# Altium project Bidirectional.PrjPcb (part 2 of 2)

## Sheet bidirectional-Phase2&3.SchDoc: Phase 2 and 3
size 431 x 279 mm; Date: Not shown in title block; ApprovedBy: Not shown in title block; CheckedBy: Not shown in title block; Author: Not shown in title block; CompanyName: Not shown in title block; Engineer: Not shown in title block; Organization: Not shown in title block; Address1: Not shown in title block; Address2: Not shown in title block; Address3: Not shown in title block; Address4: Not shown in title block; DocumentNumber: 5; Revision: Use project parameter SCH_Rev; SheetNumber: 5; SheetTotal: 6; PageSetup: Record=PageOptions|CenterHorizontal=True|CenterVertical=True|PrintScale=0.96|XCorrection=1.00|YCorrection=1.00|PrintKind=0|BorderSize=5000000|LeftOffset=0|BottomOffset=0|Orientation=2|PaperLength=1000|PaperWidth=1000|Scale=100|PaperSource=15|PrintQuality=600|MediaType=1|DitherType=10|PaperKind=11x17|PrintScaleMode=1
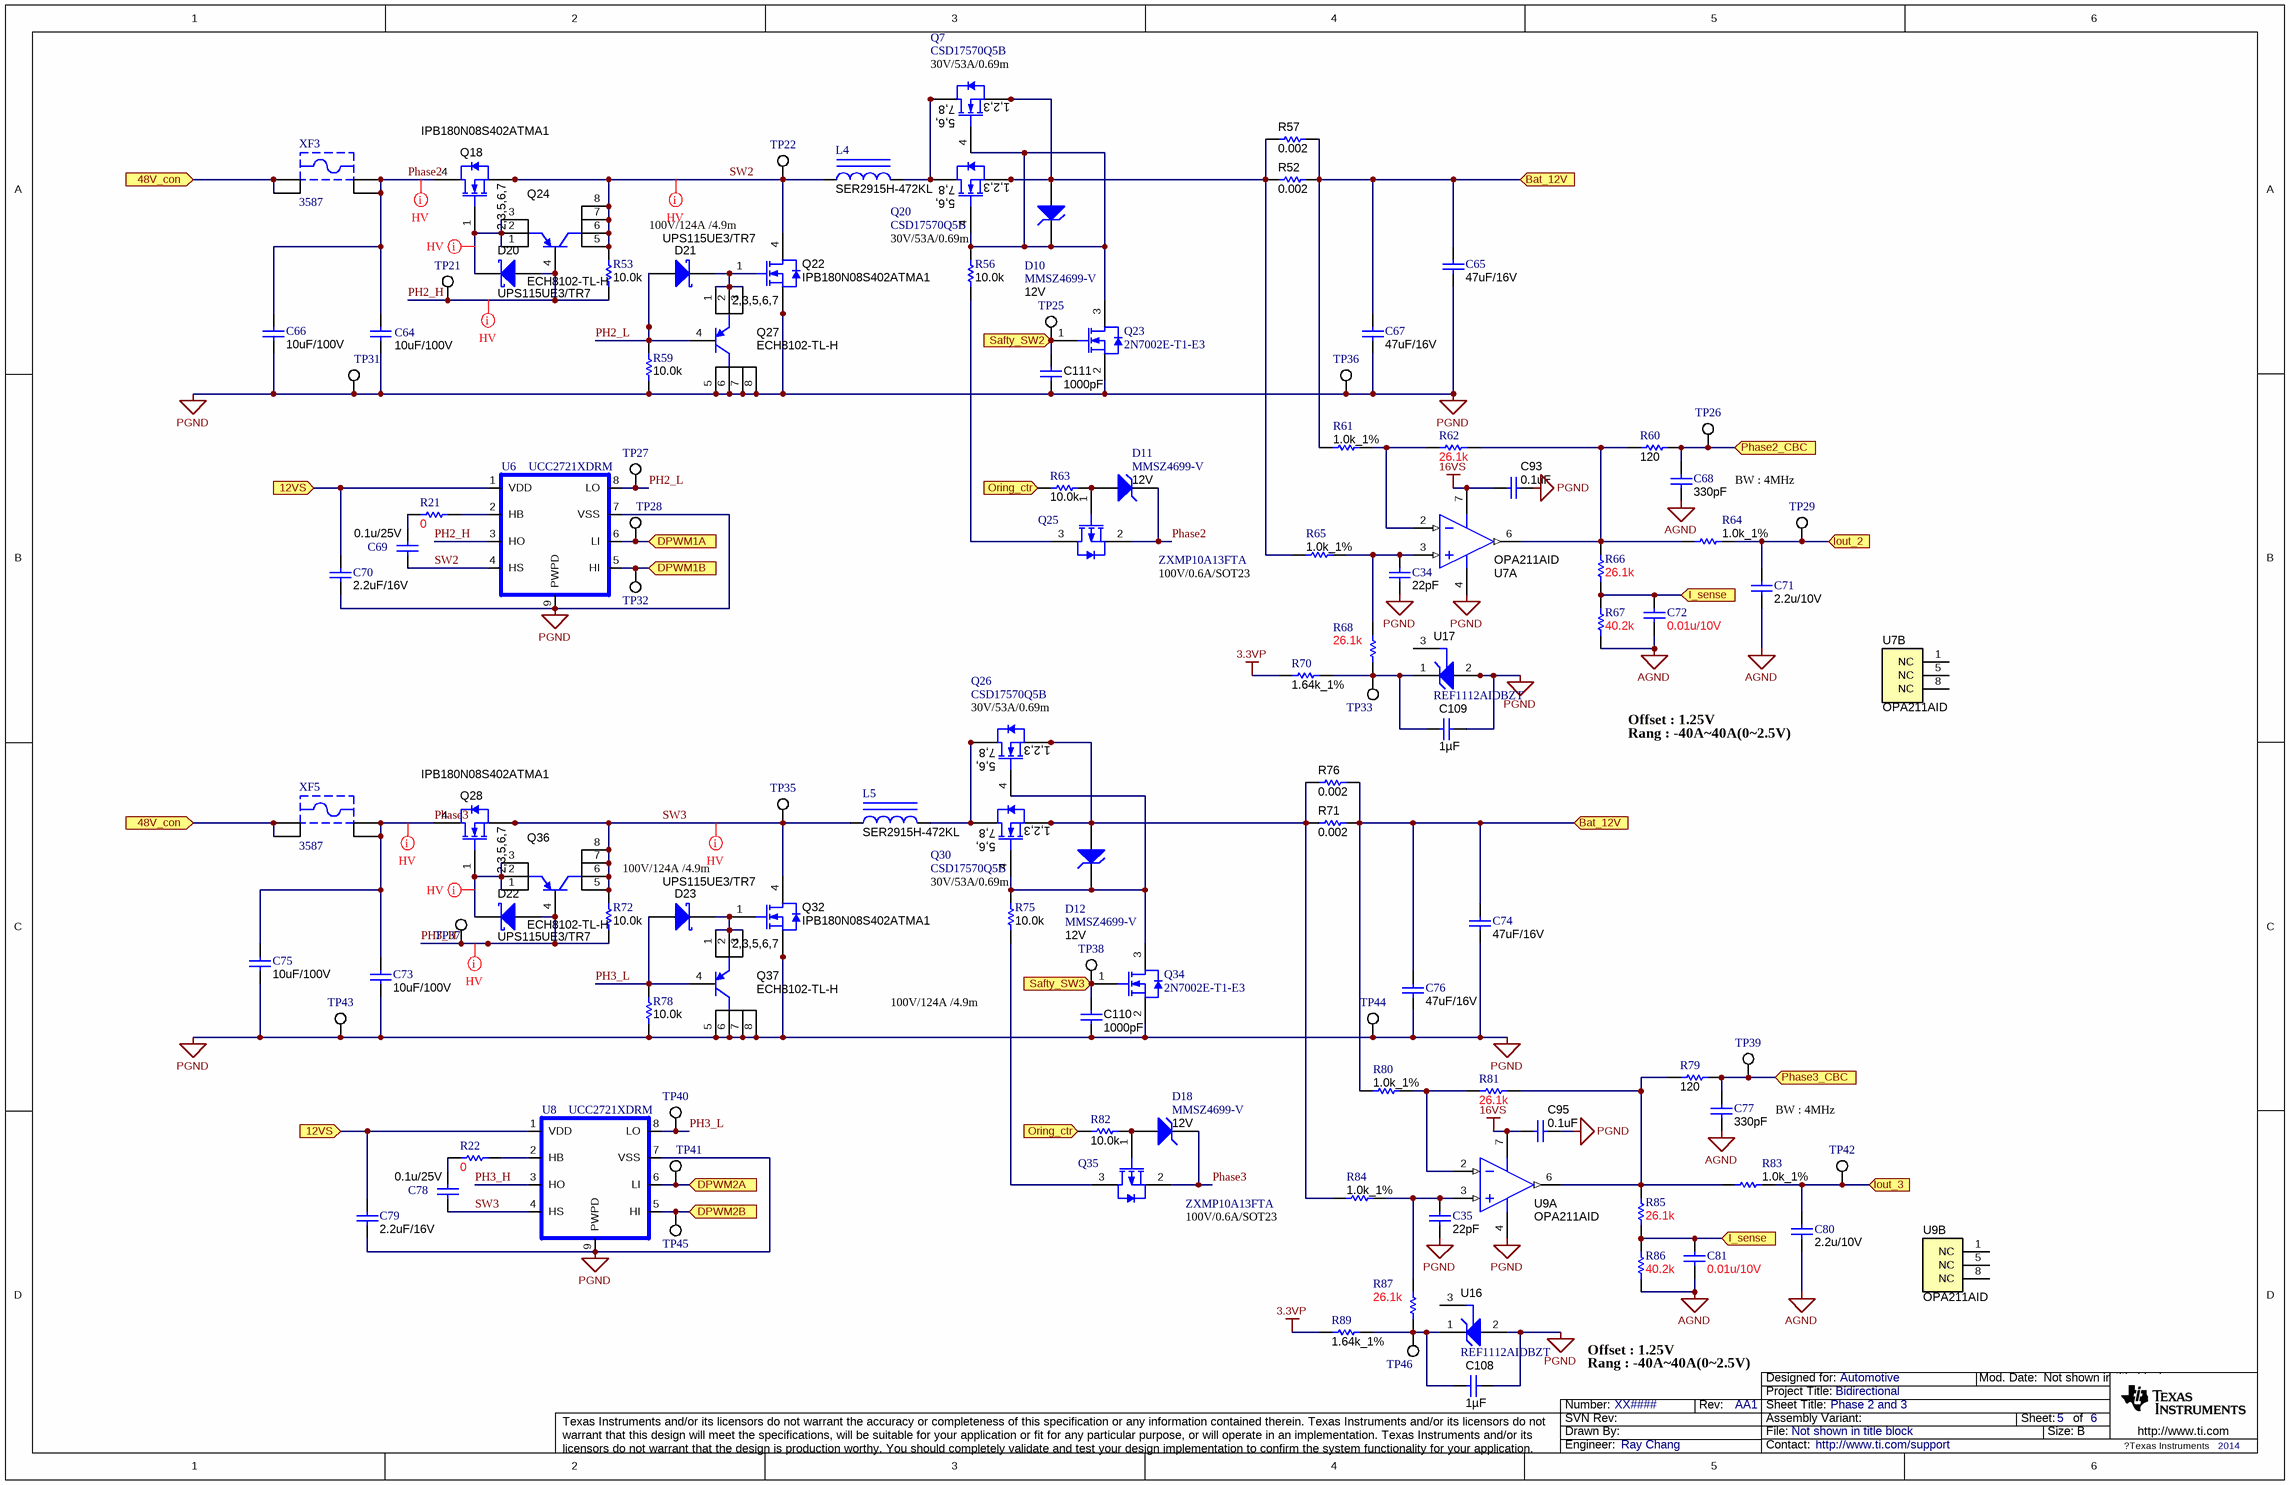
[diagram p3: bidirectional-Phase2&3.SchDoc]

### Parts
C34  ValueDisplayed: 22pF  [0603]  (hidden comment: 06035A220JAT2A)
C35  ValueDisplayed: 22pF  [0603]  (hidden comment: 06035A220JAT2A)
C64  ValueDisplayed: 10uF/100V  [2220]  (hidden comment: C5750X7S2A106M)
C65  ValueDisplayed: 47uF/16V  [1210]  (hidden comment: GRM32ER61C476ME15L)
C66  ValueDisplayed: 10uF/100V  [2220]  (hidden comment: C5750X7S2A106M)
C67  ValueDisplayed: 47uF/16V  [1210]  (hidden comment: GRM32ER61C476ME15L)
C68  ValueDisplayed: 330pF  [0603]  (hidden comment: 06035A331JAT2A)
C69  ValueDisplayed: 0.1u/25V  [0603]  (hidden comment: 06033C104KAT2A)
C70  ValueDisplayed: 2.2uF/16V  [0805_HV]  (hidden comment: 0805YD225KAT2A)
C71  ValueDisplayed: 2.2u/10V  [0603]  (hidden comment: C0603C225K8PACTU)
C72  ValueDisplayed: 0.01u/10V  [0603]  (hidden comment: 06031C103JAT2A)
C73  ValueDisplayed: 10uF/100V  [2220]  (hidden comment: C5750X7S2A106M)
C74  ValueDisplayed: 47uF/16V  [1210]  (hidden comment: GRM32ER61C476ME15L)
C75  ValueDisplayed: 10uF/100V  [2220]  (hidden comment: C5750X7S2A106M)
C76  ValueDisplayed: 47uF/16V  [1210]  (hidden comment: GRM32ER61C476ME15L)
C77  ValueDisplayed: 330pF  [0603]  (hidden comment: 06035A331JAT2A)
C78  ValueDisplayed: 0.1u/25V  [0603]  (hidden comment: 06033C104KAT2A)
C79  ValueDisplayed: 2.2uF/16V  [0805_HV]  (hidden comment: 0805YD225KAT2A)
C80  ValueDisplayed: 2.2u/10V  [0603]  (hidden comment: C0603C225K8PACTU)
C81  ValueDisplayed: 0.01u/10V  [0603]  (hidden comment: 06031C103JAT2A)
C93  ValueDisplayed: 0.1uF  [0603]  (hidden comment: 06033C104JAT2A)
C95  ValueDisplayed: 0.1uF  [0603]  (hidden comment: 06033C104JAT2A)
C108  ValueDisplayed: 1µF  [0603_095]  (hidden comment: C0603C105K3RACTU)
C109  ValueDisplayed: 1µF  [0603_095]  (hidden comment: C0603C105K3RACTU)
C110  ValueDisplayed: 1000pF  [0603]  (hidden comment: C0603X102K5RACTU)
C111  ValueDisplayed: 1000pF  [0603]  (hidden comment: C0603X102K5RACTU)
D10  MMSZ4699-V  value 12V  [SOD-123]
D11  MMSZ4699-V  value 12V  [SOD-123]
D12  MMSZ4699-V  value 12V  [SOD-123]
D18  MMSZ4699-V  value 12V  [SOD-123]
D20  UPS115UE3/TR7  [DO-216AA]
D21  UPS115UE3/TR7  [DO-216AA]
D22  UPS115UE3/TR7  [DO-216AA]
D23  UPS115UE3/TR7  [DO-216AA]
L4  SER2915H-472KL  [SER2915H]
L5  SER2915H-472KL  [SER2915H]
Q7  CSD17570Q5B  [TRANS_NexFET_Q5B]
Q18  IPB180N08S402ATMA1  [DDPAK-7]
Q20  CSD17570Q5B  [TRANS_NexFET_Q5B]
Q22  IPB180N08S402ATMA1  [DDPAK-7]
Q23  2N7002E-T1-E3  [SOT-23]
Q24  ECH8102-TL-H  [ECH8]
Q25  ZXMP10A13FTA  [SOT-23]
Q26  CSD17570Q5B  [TRANS_NexFET_Q5B]
Q27  ECH8102-TL-H  [ECH8]
Q28  IPB180N08S402ATMA1  [DDPAK-7]
Q30  CSD17570Q5B  [TRANS_NexFET_Q5B]
Q32  IPB180N08S402ATMA1  [DDPAK-7]
Q34  2N7002E-T1-E3  [SOT-23]
Q35  ZXMP10A13FTA  [SOT-23]
Q36  ECH8102-TL-H  [ECH8]
Q37  ECH8102-TL-H  [ECH8]
R21  value 0  [0603]  (hidden comment: MCR03EZPJ000)
R22  value 0  [0603]  (hidden comment: MCR03EZPJ000)
R52  ValueDisplayed: 0.002  [2512]  (hidden comment: ERJ-M1WTF2M0U)
R53  value 10.0k  [0603]  (hidden comment: RG1608P-103-B-T5)
R56  ValueDisplayed: 10.0k  [0603]  (hidden comment: CRCW060310K0FKEA)
R57  ValueDisplayed: 0.002  [2512]  (hidden comment: ERJ-M1WTF2M0U)
R59  value 10.0k  [0603]  (hidden comment: RG1608P-103-B-T5)
R60  ValueDisplayed: 120  [0603]  (hidden comment: CRCW0603120RJNEA)
R61  value 1.0k_1%  [0603]  (hidden comment: CRCW06031K00JNEA)
R62  value 26.1k  [0603]  (hidden comment: CRCW060326K1FKEA)
R63  ValueDisplayed: 10.0k  [0603]  (hidden comment: CRCW060310K0FKEA)
R64  value 1.0k_1%  [0603]  (hidden comment: CRCW06031K00JNEA)
R65  value 1.0k_1%  [0603]  (hidden comment: CRCW06031K00JNEA)
R66  value 26.1k  [0603]  (hidden comment: CRCW060326K1FKEA)
R67  value 40.2k  [0603]  (hidden comment: CRCW060340K2FKEA)
R68  value 26.1k  [0603]  (hidden comment: CRCW060326K1FKEA)
R70  value 1.64k_1%  [0603]  (hidden comment: CRCW06031K65FKEA)
R71  ValueDisplayed: 0.002  [2512]  (hidden comment: ERJ-M1WTF2M0U)
R72  value 10.0k  [0603]  (hidden comment: RG1608P-103-B-T5)
R75  ValueDisplayed: 10.0k  [0603]  (hidden comment: CRCW060310K0FKEA)
R76  ValueDisplayed: 0.002  [2512]  (hidden comment: ERJ-M1WTF2M0U)
R78  value 10.0k  [0603]  (hidden comment: RG1608P-103-B-T5)
R79  ValueDisplayed: 120  [0603]  (hidden comment: CRCW0603120RJNEA)
R80  value 1.0k_1%  [0603]  (hidden comment: CRCW06031K00JNEA)
R81  value 26.1k  [0603]  (hidden comment: CRCW060326K1FKEA)
R82  ValueDisplayed: 10.0k  [0603]  (hidden comment: CRCW060310K0FKEA)
R83  value 1.0k_1%  [0603]  (hidden comment: CRCW06031K00JNEA)
R84  value 1.0k_1%  [0603]  (hidden comment: CRCW06031K00JNEA)
R85  value 26.1k  [0603]  (hidden comment: CRCW060326K1FKEA)
R86  value 40.2k  [0603]  (hidden comment: CRCW060340K2FKEA)
R87  value 26.1k  [0603]  (hidden comment: CRCW060326K1FKEA)
R89  value 1.64k_1%  [0603]  (hidden comment: CRCW06031K65FKEA)
TP21  5002  [Keystone5002]  (value not drawn)
TP22  5002  [Keystone5002]  (value not drawn)
TP25  5002  [Keystone5002]  (value not drawn)
TP26  5002  [Keystone5002]  (value not drawn)
TP27  5002  [Keystone5002]  (value not drawn)
TP28  5002  [Keystone5002]  (value not drawn)
TP29  5002  [Keystone5002]  (value not drawn)
TP31  5002  [Keystone5002]  (value not drawn)
TP32  5002  [Keystone5002]  (value not drawn)
TP33  5002  [Keystone5002]  (value not drawn)
TP35  5002  [Keystone5002]  (value not drawn)
TP36  5002  [Keystone5002]  (value not drawn)
TP37  5002  [Keystone5002]  (value not drawn)
TP38  5002  [Keystone5002]  (value not drawn)
TP39  5002  [Keystone5002]  (value not drawn)
TP40  5002  [Keystone5002]  (value not drawn)
TP41  5002  [Keystone5002]  (value not drawn)
TP42  5002  [Keystone5002]  (value not drawn)
TP43  5002  [Keystone5002]  (value not drawn)
TP44  5002  [Keystone5002]  (value not drawn)
TP45  5002  [Keystone5002]  (value not drawn)
TP46  5002  [Keystone5002]  (value not drawn)
U6  UCC2721XDRM  [DRM0008A]
U7  OPA211AID  [D0008A_N]  (parts A,B of 2)
U8  UCC2721XDRM  [DRM0008A]
U9  OPA211AID  [D0008A_N]  (parts A,B of 2)
U16  REF1112AIDBZT  [DBZ0003A_N]
U17  REF1112AIDBZT  [DBZ0003A_N]
XF3  3587  [KEYSTONE_3587]
XF5  3587  [KEYSTONE_3587]

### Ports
12VS, 48V_con, Bat_12V, DPWM1A, DPWM1B, DPWM2A, DPWM2B, I_sense, Iout_2, Iout_3, Oring_ctr, Phase2_CBC, Phase3_CBC, Safty_SW2, Safty_SW3

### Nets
3.3VP: R70.1 R89.1
16VS: C93.2 C95.2 U7.7(V+) U9.7(V+)
AGND: C68.2 C71.2 C72.2 C77.2 C80.2 C81.2 R67.1 R86.1
PGND: C34.2 C35.2 C64.2 C65.2 C66.2 C67.2 C70.2 C73.2 C74.2 C75.2 C76.2 C79.2 C93.1 C95.1 C108.1 C109.1 C110.2 C111.2 Q22.2(S) Q22.3(S) Q22.5(S) Q22.6(S) Q22.7(S) Q23.2(S) Q27.5(C) Q27.6(C) Q27.7(C) Q27.8(C) Q32.2(S) Q32.3(S) Q32.5(S) Q32.6(S) Q32.7(S) Q34.2(S) Q37.5(C) Q37.6(C) Q37.7(C) Q37.8(C) R59.1 R78.1 TP31.1 TP36.1 TP43.1 TP44.1 U6.7(VSS) U6.9(PWPD) U7.4(V-) U8.7(VSS) U8.9(PWPD) U9.4(V-) U16.2(GND) U17.2(GND)
12VS: C70.1 C79.1 U6.1(VDD) U8.1(VDD) ; port 12VS
48V_con: XF3.1 XF3.2 XF5.1 XF5.2 ; port 48V_con
Bat_12V: C65.1 C67.1 C74.1 C76.1 R52.2 R57.2 R61.1 R71.2 R76.2 R80.1 ; port Bat_12V
DPWM1A: TP28.1 U6.6(LI) ; port DPWM1A
DPWM1B: TP32.1 U6.5(HI) ; port DPWM1B
DPWM2A: TP41.1 U8.6(LI) ; port DPWM2A
DPWM2B: TP45.1 U8.5(HI) ; port DPWM2B
I_sense: C72.1 C81.1 R66.1 R67.2 R85.1 R86.2 ; port I_sense
Iout_2: C71.1 R64.2 TP29.1 ; port Iout_2
Iout_3: C80.1 R83.2 TP42.1 ; port Iout_3
Oring_ctr: R63.2 R82.2 ; port Oring_ctr
PH2_H: D20.2(A) Q24.4(B) R53.1 TP21.1 U6.3(HO)
PH2_L: D21.2(A) Q27.4(B) R59.2 TP27.1 U6.8(LO)
PH3_H: D22.2(A) Q36.4(B) R72.1 TP37.1 U8.3(HO)
PH3_L: D23.2(A) Q37.4(B) R78.2 TP40.1 U8.8(LO)
Phase2: C64.1 C66.1 D11.1(K) Q18.4(D) Q25.2(S) XF3.3 XF3.4
Phase2_CBC: C68.1 R60.2 TP26.1 ; port Phase2_CBC
Phase3: C73.1 C75.1 D18.1(K) Q28.4(D) Q35.2(S) XF5.3 XF5.4
Phase3_CBC: C77.1 R79.2 TP39.1 ; port Phase3_CBC
Safty_SW2: C111.1 Q23.1(G) TP25.1 ; port Safty_SW2
Safty_SW3: C110.1 Q34.1(G) TP38.1 ; port Safty_SW3
SW2: C69.2 L4.1 Q18.2(S) Q18.3(S) Q18.5(S) Q18.6(S) Q18.7(S) Q22.4(D) Q24.5(C) Q24.6(C) Q24.7(C) Q24.8(C) R53.2 TP22.1 U6.4(HS)
SW3: C78.2 L5.1 Q28.2(S) Q28.3(S) Q28.5(S) Q28.6(S) Q28.7(S) Q32.4(D) Q36.5(C) Q36.6(C) Q36.7(C) Q36.8(C) R72.2 TP35.1 U8.4(HS)
NetC34_1: C34.1 R65.2 R68.2 U7.3(IN+)
NetC35_1: C35.1 R84.2 R87.2 U9.3(IN+)
NetC69_1: C69.1 R21.1
NetC78_1: C78.1 R22.1
NetC108_2: C108.2 R87.1 R89.2 TP46.1 U16.1(VO)
NetC109_2: C109.2 R68.1 R70.2 TP33.1 U17.1(VO)
NetD10_1: D10.1(K) Q7.4(G) Q20.4(G) Q23.3(D) R56.2
NetD10_2: D10.2(A) Q7.1(S) Q7.2(S) Q7.3(S) Q20.1(S) Q20.2(S) Q20.3(S) R52.1 R57.1 R65.1
NetD11_2: D11.2(A) Q25.1(G) R63.1
NetD12_1: D12.1(K) Q26.4(G) Q30.4(G) Q34.3(D) R75.2
NetD12_2: D12.2(A) Q26.1(S) Q26.2(S) Q26.3(S) Q30.1(S) Q30.2(S) Q30.3(S) R71.1 R76.1 R84.1
NetD18_2: D18.2(A) Q35.1(G) R82.1
NetD20_1: D20.1(K) Q18.1(G) Q24.1(E) Q24.2(E) Q24.3(E)
NetD21_1: D21.1(K) Q22.1(G) Q27.1(E) Q27.2(E) Q27.3(E)
NetD22_1: D22.1(K) Q28.1(G) Q36.1(E) Q36.2(E) Q36.3(E)
NetD23_1: D23.1(K) Q32.1(G) Q37.1(E) Q37.2(E) Q37.3(E)
NetL4_2: L4.2 Q7.5(D) Q7.6(D) Q7.7(D) Q7.8(D) Q20.5(D) Q20.6(D) Q20.7(D) Q20.8(D)
NetL5_2: L5.2 Q26.5(D) Q26.6(D) Q26.7(D) Q26.8(D) Q30.5(D) Q30.6(D) Q30.7(D) Q30.8(D)
NetQ25_3: Q25.3(D) R56.1
NetQ35_3: Q35.3(D) R75.1
NetR21_2: R21.2 U6.2(HB)
NetR22_2: R22.2 U8.2(HB)
NetR60_1: R60.1 R62.2 R64.1 R66.2 U7.6(OUT)
NetR61_2: R61.2 R62.1 U7.2(IN-)
NetR79_1: R79.1 R81.2 R83.1 R85.2 U9.6(OUT)
NetR80_2: R80.2 R81.1 U9.2(IN-)

Not connected (* = marked no-connect by the designer): U7 1(NC) 5(NC) 8(NC); U9 1(NC) 5(NC) 8(NC); U16 3(NC); U17 3(NC)

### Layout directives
net class HV: NetD20_1, NetD22_1, PH2_H, PH3_H, Phase2, Phase3, SW2, SW3

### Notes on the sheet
- (near Q7) 30V/53A/0.69m
- 100V/124A /4.9m
- (near R56) 30V/53A/0.69m
- BW : 4MHz
- 100V/0.6A/SOT23
- (near Q26) 30V/53A/0.69m
- Offset : 1.25V
- Rang : -40A~40A(0|.5V)
- (near R75) 30V/53A/0.69m

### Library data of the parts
C34 C35 = 06035A220JAT2A: CAP, CERM, 22pF, 50V, +/-5%, C0G/NP0, 0603; Manufacturer: AVX; Polarized: N; CompType: Capacitor; U/M: EA; Cap_F: 0.000000000022; Tolerance_%: 5; ESR_Ohm: 0.259; Value1: 0.259 ohm; VDC_V: 50; TaMin_C: -55; TaMax_C: 125
C64 C66 C73 C75 = C5750X7S2A106M: CAP, CERM, 10uF, 100V, +/-20%, X7S, 2220; Manufacturer: TDK; Polarized: N; CompType: Capacitor; U/M: EA; Cap_F: 0.00001; Tolerance_%: 20; ESR_Ohm: 0.005; Value1: 0.005 ohm; VDC_V: 100; IRMS_A: 6.45; TaMin_C: -55; TaMax_C: 125
C65 C67 C74 C76 = GRM32ER61C476ME15L: CAP, CERM, 47uF, 16V, +/-20%, X5R, 1210; Manufacturer: MuRata; Polarized: N; CompType: Capacitor; U/M: EA; Cap_F: 0.000047; Tolerance_%: 20; ESR_Ohm: 0.002; Value1: 0.002 ohm; VDC_V: 16; TaMin_C: -55; TaMax_C: 85
C68 C77 = 06035A331JAT2A: CAP, CERM, 330pF, 50V, +/-5%, C0G/NP0, 0603; Manufacturer: AVX; Polarized: N; CompType: Capacitor; U/M: EA; Cap_F: 0.00000000033; Tolerance_%: 5; ESR_Ohm: 0.071; Value1: 0.071 ohm; VDC_V: 50; TaMin_C: -55; TaMax_C: 125
C69 C78 = 06033C104KAT2A: CAP, CERM, 0.1uF, 25V, +/-10%, X7R, 0603; Manufacturer: AVX; Polarized: N; CompType: Capacitor; U/M: EA; Cap_F: 0.0000001; Tolerance_%: 10; ESR_Ohm: 0.05; Value1: 0.05 ohm; VDC_V: 25; TaMin_C: -55; TaMax_C: 125
C70 C79 = 0805YD225KAT2A: CAP, CERM, 2.2uF, 16V, +/-10%, X5R, 0805; Manufacturer: AVX; Polarized: N; CompType: Capacitor; U/M: EA; Cap_F: 0.0000022; Tolerance_%: 10; ESR_Ohm: 0.009; Value1: 0.009 ohm; VDC_V: 16; TaMin_C: -55; TaMax_C: 85; Cap_Case: 0805
C71 C80 = C0603C225K8PACTU: CAP, CERM, 2.2uF, 10V, +/-10%, X5R, 0603; Manufacturer: Kemet; Polarized: N; CompType: Capacitor; U/M: EA; Cap_F: 0.0000022; Tolerance_%: 10; Value1: Unknown; TaMin_C: -55; TaMax_C: 85
C72 C81 = 06031C103JAT2A: CAP, CERM, 0.01uF, 100V, +/-5%, X7R, 0603; Manufacturer: AVX; Polarized: N; CompType: Capacitor; U/M: EA; Cap_F: 0.00000001; Tolerance_%: 5; ESR_Ohm: 0.098; Value1: 0.098 ohm; VDC_V: 100; TaMin_C: -55; TaMax_C: 125
C93 C95 = 06033C104JAT2A: CAP, CERM, 0.1uF, 25V, +/-5%, X7R, 0603; Manufacturer: AVX; Polarized: N; CompType: Capacitor; U/M: EA; Cap_F: 0.0000001; Tolerance_%: 5; ESR_Ohm: 0.05; Value1: 0.05 ohm; VDC_V: 25; TaMin_C: -55; TaMax_C: 125
C108 C109 = C0603C105K3RACTU: CAP, CERM, 1 µF, 25 V, +/- 10%, X7R, 0603_095; Manufacturer: Kemet; Polarized: N; CompType: Capacitor; Value: 1uF; U/M: EA; Cap_F: 0.000001; Tolerance_%: 10; Value1: Unknown; VDC_V: 25; Value2: 25V; TaMin_C: -55; TaMax_C: 125; Cap_Case: 0603
C110 C111 = C0603X102K5RACTU: CAP, CERM, 1000 pF, 50 V, +/- 10%, X7R, 0603; Manufacturer: Kemet; Polarized: N; CompType: Capacitor; Value: 1000pF; U/M: EA; Cap_F: 0.000000001; Tolerance_%: 10; Value1: Unknown; VDC_V: 50; Value2: 50V; TaMin_C: -55; TaMax_C: 125
D10-D12 D18 = MMSZ4699-V: Diode, Zener, 12V, 500mW, SOD-123; Manufacturer: Vishay-Semiconductor; SymbolCreator: a0412235; U/M: EA; Power_W: 0.5; Vz_V: 12; Value1: 0.5W; RJA_CperW: 67
D20-D23 = UPS115UE3/TR7: Diode, Schottky, 15 V, 1 A, DO-216-AA; Manufacturer: Microsemi; U/M: EA; Vf_V: 0.31; Value: 15V; Value1: 1A; Value2: 0.31V; Io_A: 1; Vr_V: 15; TJmax_C: 100
L4 L5 = SER2915H-472KL: Inductor, Shielded E Core, Ferrite, 4.7 µH, 30 A, 0.00186 ohm, SMD; Manufacturer: Coilcraft; Value: 4.7uH; Ind_H: 4.7E-6; ValueDisplayed: 4.7µH; Imax_A: 30; Irms: 30A @ 40C rise; Isat: 50.1A @ 30% inductance drop; Value2: 30A
Q7 Q20 Q26 Q30 = CSD17570Q5B: MOSFET, N-CH, 30V, 51A, SON 5x6mm; Manufacturer: Texas Instruments; Alternate Manufacturer: None; U/M: EA; ChType: N; VdsMax_V: 30; Value1: 0.0076 ohm; Rdson45_Ohm: 0.0076; Value2: 97 nC; QgTyp_nC: 97; Vgs_V: 20; IdsMax_A: 51
Q18 Q22 Q28 Q32 = IPB180N08S402ATMA1: MOSFET, N-CH, 80 V, 180 A, DDPAK-7; Manufacturer: Infineon Technologies; Alternate Manufacturer: None; SymbolCreator: a0412235; U/M: EA; ChType: N; Value: 80V; VdsMax_V: 80; Value1: ? ohm; Value2: 128 nC; QgTyp_nC: 128; Vgs_V: 20; IdsMax_A: 180
Q23 Q34 = 2N7002E-T1-E3: MOSFET, N-CH, 60V, 0.24A, SOT-23; Manufacturer: Vishay-Siliconix; Alternate Manufacturer: None; U/M: EA; ChType: N; VdsMax_V: 60; Value1: 1.8 ohm; Rdson45_Ohm: 1.8; Value2: 0.4 nC; QgTyp_nC: 0.4; Vgs_V: 20; IdsMax_A: 0.24
Q24 Q27 Q36 Q37 = ECH8102-TL-H, ON Semiconductor: Transistor, PNP, 30 V, 12 A, SMD-8; CompType: BJT; PNP: 1; NPN: 0; Vceo_V: 30; Vcesat1_V: 0.08; Value: 30 V; IcRated_A: 12; Value1: 12 A; HfeMax: 560; TaMin_C: -55; TaMax_C: 150; U/M: EA
Q25 Q35 = ZXMP10A13FTA: MOSFET, P-CH, -100V, -0.6A, SOT-23; Manufacturer: Diodes Inc.; Alternate Manufacturer: None; U/M: EA; ChType: P; VdsMax_V: -100; Value1: 1 ohm; Rdson45_Ohm: 1; Value2: 3.5 nC; QgTyp_nC: 3.5; Vgs_V: -4; IdsMax_A: -0.6
R21 R22 = MCR03EZPJ000: RES, 0 ohm, 5%, 0.1W, 0603; Manufacturer: Rohm; CompType: Resistor; Value_Code: 0000; Tolerance_%: 5; Power_W: 0.1; VDC_V: 50; TempCo: 400 ppm/C; EIA_Code: E24; U/M: EA
R52 R57 R71 R76 = ERJ-M1WTF2M0U: RES, 0.002, 1%, 1 W, 2512; Manufacturer: Panasonic; CompType: Resistor; Value: 0.002; Value_Code: 2L000; Tolerance_%: 1; Value2: 1W; TempCo: ppm/C; U/M: EA
R53 R59 R72 R78 = RG1608P-103-B-T5: RES, 10.0k ohm, 0.1%, 0.1W, 0603; Manufacturer: Susumu Co Ltd; CompType: Resistor; Res_ohm: 10000; Value_Code: 10k0; Tolerance_%: 0.1; VDC_V: 75; TempCo: 25 ppm/C; EIA_Code: E192; U/M: EA
R56 R63 R75 R82 = CRCW060310K0FKEA: RES, 10.0 k, 1%, 0.1 W, 0603; Manufacturer: Vishay-Dale; CompType: Resistor; Value: 10.0k; Res_ohm: 10000; Value_Code: 10k0; Tolerance_%: 1; Power_W: 0.1; Value2: 0.1W; VDC_V: 75; TempCo: 100 ppm/C; EIA_Code: E96; U/M: EA
R60 R79 = CRCW0603120RJNEA: RES, 120, 5%, 0.1 W, 0603; Manufacturer: Vishay-Dale; CompType: Resistor; Value: 120; Value_Code: 120R; Tolerance_%: 5; Power_W: 0.1; Value2: 0.1W; VDC_V: 75; TempCo: 200 ppm/C; EIA_Code: E24; U/M: EA
R61 R64 R65 R80 R83 R84 = CRCW06031K00JNEA: RES, 1.0k ohm, 5%, 0.1W, 0603; Manufacturer: Vishay-Dale; CompType: Resistor; Res_ohm: 1000; Value_Code: 1k00; Tolerance_%: 5; Power_W: 0.1; VDC_V: 75; TempCo: 200 ppm/C; EIA_Code: E24; U/M: EA
R62 R66 R68 R81 R85 R87 = CRCW060326K1FKEA: RES, 26.1k ohm, 1%, 0.1W, 0603; Manufacturer: Vishay-Dale; CompType: Resistor; Res_ohm: 26100; Value_Code: 26k1; Tolerance_%: 1; Power_W: 0.1; VDC_V: 75; TempCo: 100 ppm/C; EIA_Code: E96; U/M: EA
R67 R86 = CRCW060340K2FKEA: RES, 40.2k ohm, 1%, 0.1W, 0603; Manufacturer: Vishay-Dale; CompType: Resistor; Res_ohm: 40200; Value_Code: 40k2; Tolerance_%: 1; Power_W: 0.1; VDC_V: 75; TempCo: 100 ppm/C; EIA_Code: E96; U/M: EA
R70 R89 = CRCW06031K65FKEA: RES, 1.65k ohm, 1%, 0.1W, 0603; Manufacturer: Vishay-Dale; CompType: Resistor; Res_ohm: 1650; Value_Code: 1k65; Tolerance_%: 1; Power_W: 0.1; VDC_V: 75; TempCo: 100 ppm/C; EIA_Code: E96; U/M: EA
TP21 TP22 TP25-TP29 TP31-TP33 TP35-TP46 = 5002: Test Point, Miniature, White, TH; Manufacturer: Keystone; CompType: Test Point Loop; U/M: EA
U6 U8 = UCC2721XDRM: IC, 120V Boot, 4A Peak, High Frequency High-Side Low-Side Driver; Manufacturer: TI; Alternate Manufacturer: None; Area: 41800
U7 U9 = OPA211AID: 1.1 nV/rtHz Noise, Low Power, Precision Operational Amplifier, 4.5 to 36 V, -40 to 125 degC, 8-pin SOIC (D0008A), Green (RoHS & no Sb/Br); Manufacturer: Texas Instruments; Alternate PartNumber: Equivalent; CMRR(Min)(dB): 114; GBW(Typ)(MHz): 45; IIB(Max)(pA): 175000; Iq per channel(Max)(mA): 4.5; Number of Channels: 1; Offset Drift(Typ)(uV/C): 0.15; Packing: TUBE; Rating: Catalog; Slew Rate(Typ)(V/us): 27; Sub Family: High Supply Voltage Amplifier (>=30V), Low Noise Amp (<=10nV/rtHz), Low Offset Voltage Amplifier (<=500uV), Precision Amplifier; Total Supply Voltage(Max)(+5V is 5, +/-5V is 10): 36; Vio (25C)(Max)(mV): 0.125
U16 U17 = REF1112AIDBZt: 1 uA Shunt Voltage Reference, 1.25 V, 10 ppm / degC, 5 mA, -40 to 85 degC, 3-pin SOT-23 (DBZ), Green (RoHS & no Sb/Br); Manufacturer: Texas Instruments; Alternate PartNumber: Equivalent; Initial Accuracy @ 25/deg C(%): 0.2; Iout/Iz(Max)(mA): 5; Min Iz for Regulation(uA): 1.2; Rating: Catalog; Temp Coeff(Max)(ppm/ degree C): 50; Temp Coeff(Typ)(ppm/ degree C): 10; VO(V): 1.25
XF3 XF5 = 3587: FuseHolder; Manufacturer: Keystone; SymbolCreator: a0799628

## Sheet bidirectional-Phase4.SchDoc: Phase 4
size 431 x 279 mm; Date: Not shown in title block; ApprovedBy: Not shown in title block; CheckedBy: Not shown in title block; Author: Not shown in title block; CompanyName: Not shown in title block; Engineer: Not shown in title block; Organization: Not shown in title block; Address1: Not shown in title block; Address2: Not shown in title block; Address3: Not shown in title block; Address4: Not shown in title block; DocumentNumber: 6; Revision: Use project parameter SCH_Rev; SheetNumber: 6; SheetTotal: 6; PageSetup: Record=PageOptions|CenterHorizontal=True|CenterVertical=True|PrintScale=0.96|XCorrection=1.00|YCorrection=1.00|PrintKind=0|BorderSize=5000000|LeftOffset=0|BottomOffset=0|Orientation=2|PaperLength=1000|PaperWidth=1000|Scale=100|PaperSource=15|PrintQuality=600|MediaType=1|DitherType=10|PaperKind=11x17|PrintScaleMode=1
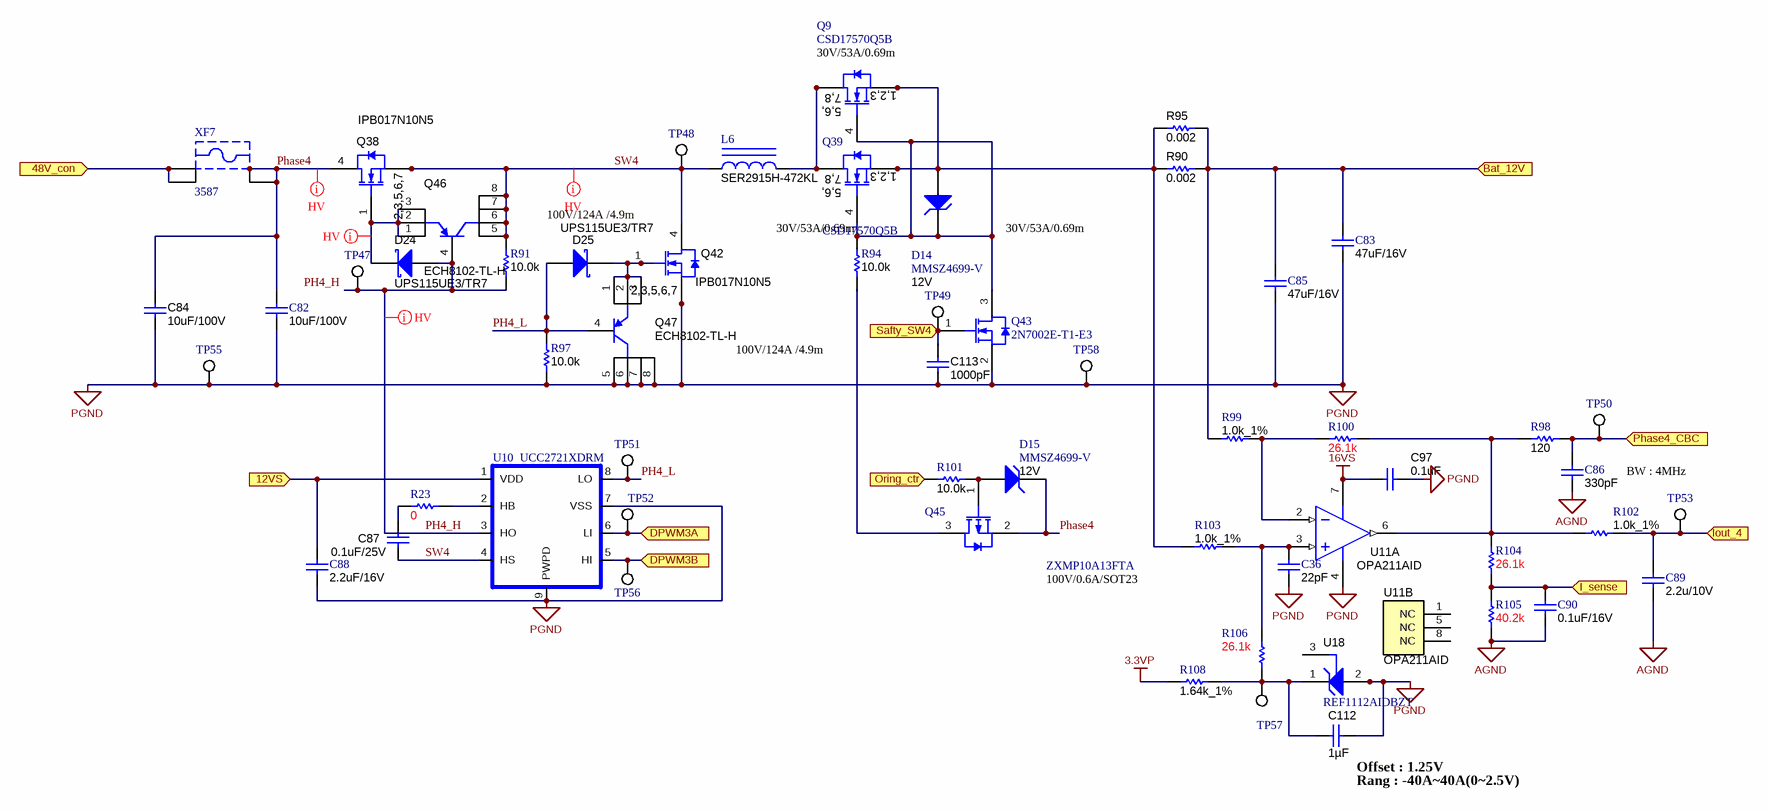
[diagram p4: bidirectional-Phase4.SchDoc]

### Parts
C36  ValueDisplayed: 22pF  [0603]  (hidden comment: 06035A220JAT2A)
C82  ValueDisplayed: 10uF/100V  [2220]  (hidden comment: C5750X7S2A106M)
C83  ValueDisplayed: 47uF/16V  [1210]  (hidden comment: GRM32ER61C476ME15L)
C84  ValueDisplayed: 10uF/100V  [2220]  (hidden comment: C5750X7S2A106M)
C85  ValueDisplayed: 47uF/16V  [1210]  (hidden comment: GRM32ER61C476ME15L)
C86  ValueDisplayed: 330pF  [0603]  (hidden comment: 06035A331JAT2A)
C87  ValueDisplayed: 0.1uF/25V  [0603]  (hidden comment: 06033C104KAT2A)
C88  ValueDisplayed: 2.2uF/16V  [0805_HV]  (hidden comment: 0805YD225KAT2A)
C89  ValueDisplayed: 2.2u/10V  [0603]  (hidden comment: C0603C225K8PACTU)
C90  ValueDisplayed: 0.1uF/16V  [0603]  (hidden comment: 0603YC104JAT2A)
C97  ValueDisplayed: 0.1uF  [0603]  (hidden comment: 06033C104JAT2A)
C112  ValueDisplayed: 1µF  [0603_095]  (hidden comment: C0603C105K3RACTU)
C113  ValueDisplayed: 1000pF  [0603]  (hidden comment: C0603X102K5RACTU)
D14  MMSZ4699-V  value 12V  [SOD-123]
D15  MMSZ4699-V  value 12V  [SOD-123]
D24  UPS115UE3/TR7  [DO-216AA]
D25  UPS115UE3/TR7  [DO-216AA]
L6  SER2915H-472KL  [SER2915H]
Q9  CSD17570Q5B  [TRANS_NexFET_Q5B]
Q38  IPB017N10N5  [DDPAK-7]
Q39  CSD17570Q5B  [TRANS_NexFET_Q5B]
Q42  IPB017N10N5  [DDPAK-7]
Q43  2N7002E-T1-E3  [SOT-23]
Q45  ZXMP10A13FTA  [SOT-23]
Q46  ECH8102-TL-H  [ECH8]
Q47  ECH8102-TL-H  [ECH8]
R23  value 0  [0603]  (hidden comment: MCR03EZPJ000)
R90  ValueDisplayed: 0.002  [2512]  (hidden comment: ERJ-M1WTF2M0U)
R91  value 10.0k  [0603]  (hidden comment: RG1608P-103-B-T5)
R94  ValueDisplayed: 10.0k  [0603]  (hidden comment: CRCW060310K0FKEA)
R95  ValueDisplayed: 0.002  [2512]  (hidden comment: ERJ-M1WTF2M0U)
R97  value 10.0k  [0603]  (hidden comment: RG1608P-103-B-T5)
R98  ValueDisplayed: 120  [0603]  (hidden comment: CRCW0603120RJNEA)
R99  value 1.0k_1%  [0603]  (hidden comment: CRCW06031K00JNEA)
R100  value 26.1k  [0603]  (hidden comment: CRCW060326K1FKEA)
R101  ValueDisplayed: 10.0k  [0603]  (hidden comment: CRCW060310K0FKEA)
R102  value 1.0k_1%  [0603]  (hidden comment: CRCW06031K00JNEA)
R103  value 1.0k_1%  [0603]  (hidden comment: CRCW06031K00JNEA)
R104  value 26.1k  [0603]  (hidden comment: CRCW060326K1FKEA)
R105  value 40.2k  [0603]  (hidden comment: CRCW060340K2FKEA)
R106  value 26.1k  [0603]  (hidden comment: CRCW060326K1FKEA)
R108  value 1.64k_1%  [0603]  (hidden comment: CRCW06031K65FKEA)
TP47  5002  [Keystone5002]  (value not drawn)
TP48  5002  [Keystone5002]  (value not drawn)
TP49  5002  [Keystone5002]  (value not drawn)
TP50  5002  [Keystone5002]  (value not drawn)
TP51  5002  [Keystone5002]  (value not drawn)
TP52  5002  [Keystone5002]  (value not drawn)
TP53  5002  [Keystone5002]  (value not drawn)
TP55  5002  [Keystone5002]  (value not drawn)
TP56  5002  [Keystone5002]  (value not drawn)
TP57  5002  [Keystone5002]  (value not drawn)
TP58  5002  [Keystone5002]  (value not drawn)
U10  UCC2721XDRM  [DRM0008A]
U11  OPA211AID  [D0008A_N]  (parts A,B of 2)
U18  REF1112AIDBZT  [DBZ0003A_N]
XF7  3587  [KEYSTONE_3587]

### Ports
12VS, 48V_con, Bat_12V, DPWM3A, DPWM3B, I_sense, Iout_4, Oring_ctr, Phase4_CBC, Safty_SW4

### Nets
3.3VP: R108.1
16VS: C97.2 U11.7(V+)
AGND: C86.2 C89.2 C90.2 R105.1
PGND: C36.2 C82.2 C83.2 C84.2 C85.2 C88.2 C97.1 C112.1 C113.2 Q42.2(S) Q42.3(S) Q42.5(S) Q42.6(S) Q42.7(S) Q43.2(S) Q47.5(C) Q47.6(C) Q47.7(C) Q47.8(C) R97.1 TP55.1 TP58.1 U10.7(VSS) U10.9(PWPD) U11.4(V-) U18.2(GND)
12VS: C88.1 U10.1(VDD) ; port 12VS
48V_con: XF7.1 XF7.2 ; port 48V_con
Bat_12V: C83.1 C85.1 R90.2 R95.2 R99.1 ; port Bat_12V
DPWM3A: TP52.1 U10.6(LI) ; port DPWM3A
DPWM3B: TP56.1 U10.5(HI) ; port DPWM3B
I_sense: C90.1 R104.1 R105.2 ; port I_sense
Iout_4: C89.1 R102.2 TP53.1 ; port Iout_4
Oring_ctr: R101.2 ; port Oring_ctr
PH4_H: D24.2(A) Q46.4(B) R91.1 TP47.1 U10.3(HO)
PH4_L: D25.2(A) Q47.4(B) R97.2 TP51.1 U10.8(LO)
Phase4: C82.1 C84.1 D15.1(K) Q38.4(D) Q45.2(S) XF7.3 XF7.4
Phase4_CBC: C86.1 R98.2 TP50.1 ; port Phase4_CBC
Safty_SW4: C113.1 Q43.1(G) TP49.1 ; port Safty_SW4
SW4: C87.2 L6.1 Q38.2(S) Q38.3(S) Q38.5(S) Q38.6(S) Q38.7(S) Q42.4(D) Q46.5(C) Q46.6(C) Q46.7(C) Q46.8(C) R91.2 TP48.1 U10.4(HS)
NetC36_1: C36.1 R103.2 R106.2 U11.3(IN+)
NetC87_1: C87.1 R23.1
NetC112_2: C112.2 R106.1 R108.2 TP57.1 U18.1(VO)
NetD14_1: D14.1(K) Q9.4(G) Q39.4(G) Q43.3(D) R94.2
NetD14_2: D14.2(A) Q9.1(S) Q9.2(S) Q9.3(S) Q39.1(S) Q39.2(S) Q39.3(S) R90.1 R95.1 R103.1
NetD15_2: D15.2(A) Q45.1(G) R101.1
NetD24_1: D24.1(K) Q38.1(G) Q46.1(E) Q46.2(E) Q46.3(E)
NetD25_1: D25.1(K) Q42.1(G) Q47.1(E) Q47.2(E) Q47.3(E)
NetL6_2: L6.2 Q9.5(D) Q9.6(D) Q9.7(D) Q9.8(D) Q39.5(D) Q39.6(D) Q39.7(D) Q39.8(D)
NetQ45_3: Q45.3(D) R94.1
NetR23_2: R23.2 U10.2(HB)
NetR98_1: R98.1 R100.2 R102.1 R104.2 U11.6(OUT)
NetR99_2: R99.2 R100.1 U11.2(IN-)

Not connected (* = marked no-connect by the designer): U11 1(NC) 5(NC) 8(NC); U18 3(NC)

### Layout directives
net class HV: NetD24_1, PH4_H, Phase4, SW4

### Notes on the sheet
- (near Q9) 30V/53A/0.69m
- 100V/124A /4.9m
- (near R94) 30V/53A/0.69m
- 30V/53A/0.69m
- BW : 4MHz
- 100V/0.6A/SOT23
- (near C112) Offset : 1.25V
- (near C112) Rang : -40A~40A(0|.5V)
- Labels drawn without touching a wire or pin: PH4_H

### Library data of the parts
C36 = 06035A220JAT2A: as C34 on sheet bidirectional-Phase2&3
C82 C84 = C5750X7S2A106M: as C64 on sheet bidirectional-Phase2&3
C83 C85 = GRM32ER61C476ME15L: as C65 on sheet bidirectional-Phase2&3
C86 = 06035A331JAT2A: as C68 on sheet bidirectional-Phase2&3
C87 = 06033C104KAT2A: as C69 on sheet bidirectional-Phase2&3
C88 = 0805YD225KAT2A: as C70 on sheet bidirectional-Phase2&3
C89 = C0603C225K8PACTU: as C71 on sheet bidirectional-Phase2&3
C90 = 0603YC104JAT2A: CAP, CERM, 0.1uF, 16V, +/-5%, X7R, 0603; Manufacturer: AVX; Polarized: N; CompType: Capacitor; U/M: EA; Cap_F: 0.0000001; Tolerance_%: 5; ESR_Ohm: 0.039; Value1: 0.039 ohm; VDC_V: 16; TaMin_C: -55; TaMax_C: 125
C97 = 06033C104JAT2A: as C93 on sheet bidirectional-Phase2&3
C112 = C0603C105K3RACTU: as C108 on sheet bidirectional-Phase2&3
C113 = C0603X102K5RACTU: as C110 on sheet bidirectional-Phase2&3
D14 D15 = MMSZ4699-V: as D10-D12 on sheet bidirectional-Phase2&3
D24 D25 = UPS115UE3/TR7: as D20-D23 on sheet bidirectional-Phase2&3
L6 = SER2915H-472KL: as L4 on sheet bidirectional-Phase2&3
Q9 Q39 = CSD17570Q5B: as Q7 on sheet bidirectional-Phase2&3
Q38 Q42 = IPB180N08S402ATMA1: as Q18 on sheet bidirectional-Phase2&3
Q43 = 2N7002E-T1-E3: as Q23 on sheet bidirectional-Phase2&3
Q45 = ZXMP10A13FTA: as Q25 on sheet bidirectional-Phase2&3
Q46 Q47 = ECH8102-TL-H, ON Semiconductor: as Q24 on sheet bidirectional-Phase2&3
R23 = MCR03EZPJ000: as R21 on sheet bidirectional-Phase2&3
R90 R95 = ERJ-M1WTF2M0U: as R52 on sheet bidirectional-Phase2&3
R91 R97 = RG1608P-103-B-T5: as R53 on sheet bidirectional-Phase2&3
R94 R101 = CRCW060310K0FKEA: as R56 on sheet bidirectional-Phase2&3
R98 = CRCW0603120RJNEA: as R60 on sheet bidirectional-Phase2&3
R99 R102 R103 = CRCW06031K00JNEA: as R61 on sheet bidirectional-Phase2&3
R100 R104 R106 = CRCW060326K1FKEA: as R62 on sheet bidirectional-Phase2&3
R105 = CRCW060340K2FKEA: as R67 on sheet bidirectional-Phase2&3
R108 = CRCW06031K65FKEA: as R70 on sheet bidirectional-Phase2&3
TP47-TP53 TP55-TP58 = 5002: as TP21 on sheet bidirectional-Phase2&3
U10 = UCC2721XDRM: as U6 on sheet bidirectional-Phase2&3
U11 = OPA211AID: as U7 on sheet bidirectional-Phase2&3
U18 = REF1112AIDBZt: as U16 on sheet bidirectional-Phase2&3
XF7 = 3587: as XF3 on sheet bidirectional-Phase2&3

## Sheet Hardware_ANSI-B.SchDoc: Hardware_ANSI-B
size 431 x 279 mm; Date: Not shown in title block; ApprovedBy: Not shown in title block; CheckedBy: Not shown in title block; Author: Not shown in title block; CompanyName: Not shown in title block; Engineer: Not shown in title block; Organization: Not shown in title block; Address1: Not shown in title block; Address2: Not shown in title block; Address3: Not shown in title block; Address4: Not shown in title block; DocumentNumber: 1; Revision: Use project parameter SCH_Rev; SheetNumber: 3; SheetTotal: 3; PageSetup: Record=PageOptions|CenterHorizontal=True|CenterVertical=True|PrintScale=1.00|XCorrection=1.00|YCorrection=1.00|PrintKind=0|BorderSize=5000000|LeftOffset=0|BottomOffset=0|Orientation=2|PaperLength=1000|PaperWidth=1000|Scale=100|PaperSource=15|PrintQuality=600|MediaType=1|DitherType=10|PaperKind=Letter|PrintScaleMode=1
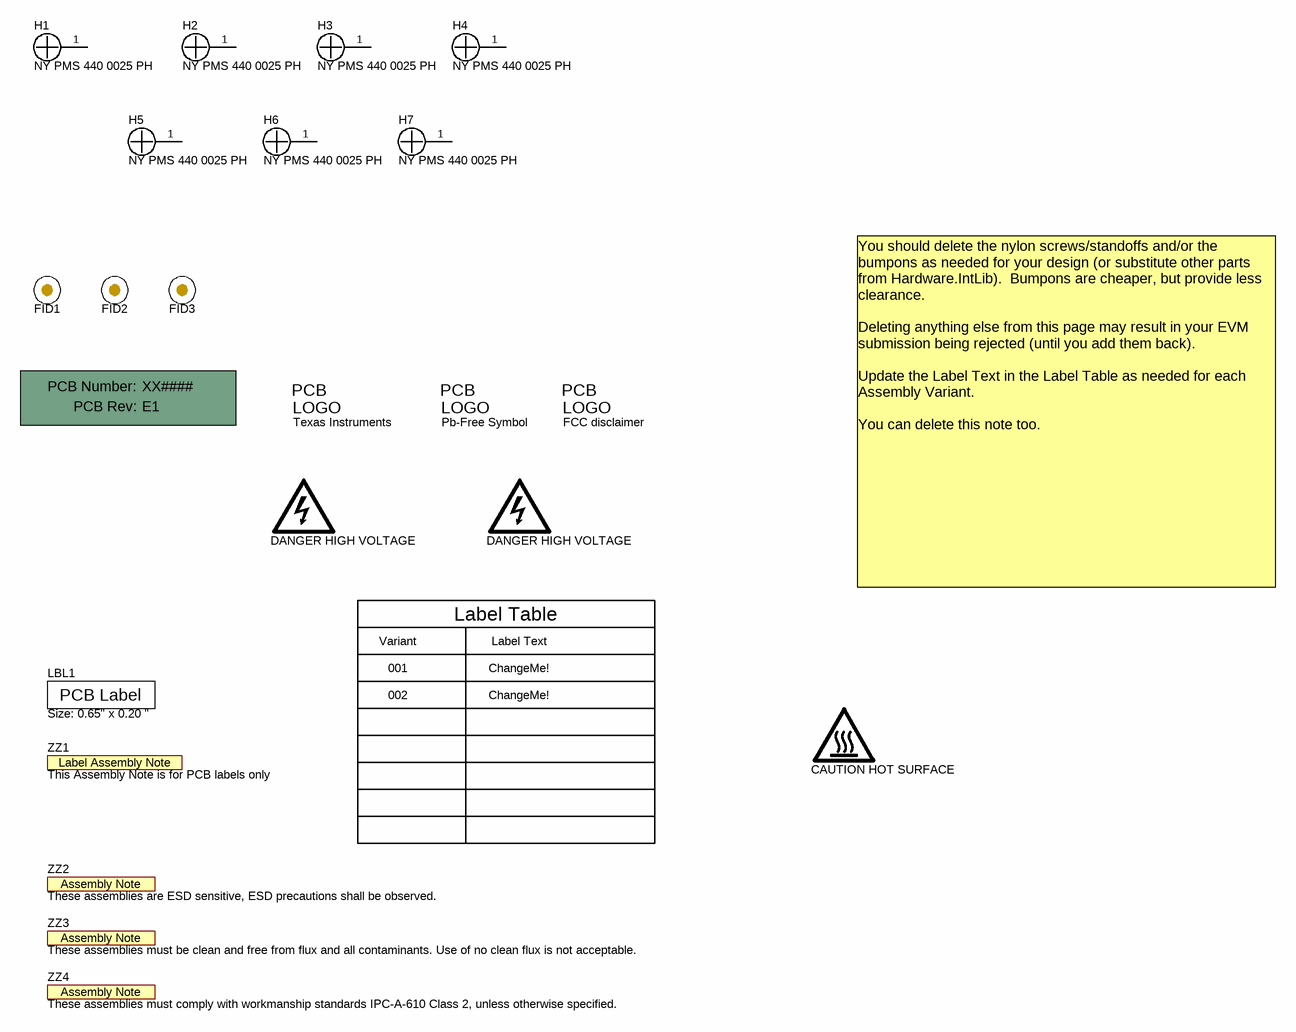
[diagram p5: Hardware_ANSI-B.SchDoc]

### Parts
!PCB  Printed Circuit Board  (value not drawn)  (mechanical)
FID1  Fiducial  [Fiducial10-20]  (value not drawn)
FID2  Fiducial  [Fiducial10-20]  (value not drawn)
FID3  Fiducial  [Fiducial10-20]  (value not drawn)
H1  NY PMS 440 0025 PH  [NY PMS 440 0025 PH]
H2  NY PMS 440 0025 PH  [NY PMS 440 0025 PH]
H3  NY PMS 440 0025 PH  [NY PMS 440 0025 PH]
H4  NY PMS 440 0025 PH  [NY PMS 440 0025 PH]
H5  NY PMS 440 0025 PH  [NY PMS 440 0025 PH]
H6  NY PMS 440 0025 PH  [NY PMS 440 0025 PH]
H7  NY PMS 440 0025 PH  [NY PMS 440 0025 PH]
LBL1  Size: 0.65" x 0.20 "  [Label_650x200]
Logo1  Texas Instruments  [TI_Stacked_Overlay_Small]  (no BOM)
Logo2  Pb-Free Symbol  [Pb-Free_Overlay_Small]  (no BOM)
Logo3  FCC disclaimer  [FCC_disclaimer]  (no BOM)
Logo4  DANGER HIGH VOLTAGE  [IEC_HighVoltage_Small]  (no BOM)
Logo5  DANGER HIGH VOLTAGE  [IEC_HighVoltage_Small]  (no BOM)
Logo6  CAUTION HOT SURFACE  [IEC_HotSurface_Small]  (no BOM)
ZZ1  This Assembly Note is for PCB labels only  [AssemblyNoteLabel]  (no BOM)
ZZ2  These assemblies are ESD sensitive, ESD precautions shall be observed.  [AssemblyNote]  (no BOM)
ZZ3  These assemblies must be clean and free from flux and all contaminants. Use of no clean flux is not acceptable.  [AssemblyNote]  (no BOM)
ZZ4  These assemblies must comply with workmanship standards IPC-A-610 Class 2, unless otherwise specified.  [AssemblyNote]  (no BOM)

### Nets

Not connected (* = marked no-connect by the designer): H1 1; H2 1; H3 1; H4 1; H5 1; H6 1; H7 1

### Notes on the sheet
- Variant
- Label Table
- Label Text
- You should delete the nylon screws/standoffs and/or the bumpons as needed for your design (or substitute other parts from Hardware.IntLib).  Bumpons are cheaper, but provide less clearance.
  Deleting anything else from this page may result in your EVM submission being rejected (until you add them back).
  Update the Label Text in the Label Table as needed for each Assembly Variant.
  You can delete this note too.
- 001
- 002
- ChangeMe!

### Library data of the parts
!PCB = PCB: Manufacturer: Any; PartNumber: XX####; SymbolCreator: a0412235
FID1-FID3 = Fiducial: Fiducial mark.  There is nothing to buy or mount.; SymbolCreator: codlsc
H1-H7 = NY PMS 440 0025 PH: Machine Screw, Round, #4-40 x 1/4, Nylon, Philips panhead; Manufacturer: B&F Fastener Supply; CompType: Hardware; SymbolCreator: codlsc; U/M: EA
LBL1 = THT-14-423-10: Thermal Transfer Printable Labels, 0.650" W x 0.200" H - 10,000 per roll; Manufacturer: Brady; SymbolCreator: a0412235; CompType: Label
Logo1 = TI_Logo: Texas Instrument Corporate Signature; SymbolCreator: codlsc
Logo2 = Pb-Free: SymbolCreator: a0412235
Logo3 = FCC_disclaimer: SymbolCreator: codlsc
Logo4 Logo5 = IEC_HighVoltage: IEC 61010-1 High Voltage Warning; SymbolCreator: a0412235
Logo6 = IEC_HotSurface: IEC 61010-1 Hot Surface Warning; SymbolCreator: a0412235
ZZ1 = AssemblyNoteLabel: SymbolCreator: a0412235
ZZ2-ZZ4 = AssemblyNote: SymbolCreator: codlsc

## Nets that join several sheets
3.3VD: Aux Power Supply (C13.1 R9.2 U2.2 U2.4), bidirectional-MCU (15 pins), bidirectional-phase1 (10 pins)
3.3VP: bidirectional-phase1 (C29.2 R51.1 R130.1 U12.8), bidirectional-Phase2&3 (R70.1 R89.1), bidirectional-Phase4 (R108.1)
16VS: Aux Power Supply (C2.1 C114.1 D1.3 D17.1), bidirectional-phase1 (C91.1 U5.8), bidirectional-Phase2&3 (C93.2 C95.2 U7.7 U9.7), bidirectional-Phase4 (C97.2 U11.7)
AGND: bidirectional-MCU (21 pins), bidirectional-phase1 (C59.2 C63.2 C94.2 R48.1), bidirectional-Phase2&3 (8 pins), bidirectional-Phase4 (C86.2 C89.2 C90.2 R105.1)
PGND: Aux Power Supply (21 pins), bidirectional-MCU (23 pins), bidirectional-phase1 (62 pins), bidirectional-Phase2&3 (52 pins), bidirectional-Phase4 (26 pins)
12VS: Aux Power Supply (5 pins), bidirectional-phase1 (C61.1 U4.1), bidirectional-Phase2&3 (C70.1 C79.1 U6.1 U8.1), bidirectional-Phase4 (C88.1 U10.1)
12Vsen: bidirectional-MCU (C27.1 R119.1 U3.66), bidirectional-phase1 (R29.1 R35.2 TP7.1)
48V_con: bidirectional-phase1 (6 pins), bidirectional-Phase2&3 (XF3.1 XF3.2 XF5.1 XF5.2), bidirectional-Phase4 (XF7.1 XF7.2)
48Vsen: bidirectional-MCU (C25.1 R117.1 U3.68), bidirectional-phase1 (R28.1 R33.2 TP6.1)
Bat_12V: Aux Power Supply (D6.2 D17.2 J11.1), bidirectional-phase1 (19 pins), bidirectional-Phase2&3 (10 pins), bidirectional-Phase4 (5 pins)
Bat_48V: Aux Power Supply (C6.1 R3.2 R4.1 U1.2), bidirectional-phase1 (7 pins)
DPWM0A: bidirectional-MCU (U3.22), bidirectional-phase1 (TP15.1 U4.6)
DPWM0B: bidirectional-MCU (U3.23), bidirectional-phase1 (TP19.1 U4.5)
DPWM1A: bidirectional-MCU (U3.24), bidirectional-Phase2&3 (TP28.1 U6.6)
DPWM1B: bidirectional-MCU (U3.25), bidirectional-Phase2&3 (TP32.1 U6.5)
DPWM2A: bidirectional-MCU (U3.26), bidirectional-Phase2&3 (TP41.1 U8.6)
DPWM2B: bidirectional-MCU (U3.27), bidirectional-Phase2&3 (TP45.1 U8.5)
DPWM3A: bidirectional-MCU (U3.28), bidirectional-Phase4 (TP52.1 U10.6)
DPWM3B: bidirectional-MCU (U3.29), bidirectional-Phase4 (TP56.1 U10.5)
I_sense: bidirectional-MCU (U3.64), bidirectional-phase1 (C63.1 R47.1 R48.2 TP18.1), bidirectional-Phase2&3 (6 pins), bidirectional-Phase4 (C90.1 R104.1 R105.2)
Iout_1: bidirectional-MCU (U3.77), bidirectional-phase1 (C94.1 R45.2 TP16.1)
Iout_2: bidirectional-MCU (U3.78), bidirectional-Phase2&3 (C71.1 R64.2 TP29.1)
Iout_3: bidirectional-MCU (U3.3), bidirectional-Phase2&3 (C80.1 R83.2 TP42.1)
Iout_4: bidirectional-MCU (U3.79), bidirectional-Phase4 (C89.1 R102.2 TP53.1)
Oring_ctr: bidirectional-phase1 (Q14.3 R33.1 R41.1), bidirectional-Phase2&3 (R63.2 R82.2), bidirectional-Phase4 (R101.2)
Phase1_CBC: bidirectional-MCU (U3.7), bidirectional-phase1 (C59.1 R42.2 TP13.1)
Phase2_CBC: bidirectional-MCU (U3.6), bidirectional-Phase2&3 (C68.1 R60.2 TP26.1)
Phase3_CBC: bidirectional-MCU (U3.4), bidirectional-Phase2&3 (C77.1 R79.2 TP39.1)
Phase4_CBC: bidirectional-MCU (U3.1), bidirectional-Phase4 (C86.1 R98.2 TP50.1)
PWM0: bidirectional-MCU (U3.39), bidirectional-phase1 (U14.3)
PWM1: bidirectional-MCU (U3.40), bidirectional-phase1 (U14.1)
Safty_SW1: bidirectional-MCU (R124.1), bidirectional-phase1 (C107.1 Q12.1 TP10.1)
Safty_SW2: bidirectional-MCU (R125.1), bidirectional-Phase2&3 (C111.1 Q23.1 TP25.1)
Safty_SW3: bidirectional-MCU (R126.1), bidirectional-Phase2&3 (C110.1 Q34.1 TP38.1)
Safty_SW4: bidirectional-MCU (R127.1), bidirectional-Phase4 (C113.1 Q43.1 TP49.1)
SYNC: bidirectional-MCU (6 pins), bidirectional-phase1 (U13.4)

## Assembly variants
001: not fitted C32 C34 C35 C36 C105 Q2 Q3 Q12 Q23 Q34 Q43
